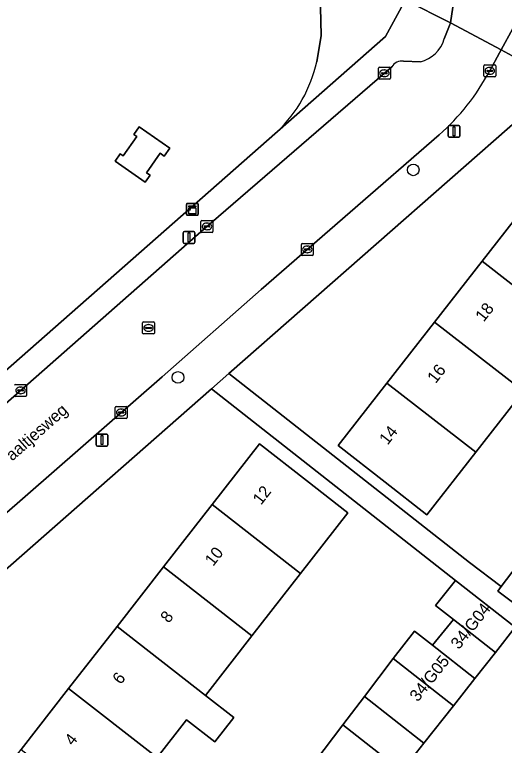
# Model space of a CAD drawing. Extents: x 158352 to 159489, y 383828 to 384603.
# Drawn here: x 158947.7 to 158988.7, y 383938.1 to 383999.4 of the extents above; entities that cross this region are included whole.
import ezdxf

# ---------------------------------------------------------------- set-up
doc = ezdxf.new("R2010")
doc.units = 0
for name, color, linetype in [('IMGEO_Boom', 7, 'Continuous'), ('IMGEO_Erf', 7, 'Continuous'), ('IMGEO_Kast', 7, 'Continuous'), ('IMGEO_Kolk', 7, 'Continuous'), ('IMGEO_Lichtmast', 7, 'Continuous'), ('IMGEO_Openbare_ruimte_label', 7, 'Continuous'), ('IMGEO_Pand', 7, 'Continuous'), ('IMGEO_Pand_nummerreeks', 7, 'Continuous'), ('IMGEO_Rijbaan_lokaal_open', 7, 'Continuous'), ('IMGEO_Rioolput', 7, 'Continuous'), ('IMGEO_Voetpad_open', 7, 'Continuous')]:
    doc.layers.add(name, color=color, linetype=linetype)

msp = doc.modelspace()

# ---------------------------------------------------------------- linework, layer by layer
at = {"layer": 'IMGEO_Boom'}
for centre in [(158981.095, 383986.358), (158961.37, 383968.951)]:
    msp.add_circle(centre, 0.489, dxfattribs=at)
at = {"layer": 'IMGEO_Erf'}
for points in [[(158973.009, 383995.42), (158973.387, 383997.64), (158973.32, 384000), (158973.14, 384001.022)], [(158990.338, 383990.981), (158965.629, 383969.277), (158985.803, 383953.421), (158988.471, 383951.405), (158990.338, 383953.876)], [(158930.848, 383955.369), (158969.722, 383989.587)], [(158989.64, 383947.992), (158987.979, 383945.879), (158986.26, 383943.692), (158984.462, 383941.404), (158981.991, 383938.261), (158980.149, 383935.918), (158977.736, 383932.848), (158975.883, 383930.491), (158973.579, 383927.56), (158971.799, 383925.296), (158967.465, 383919.782), (158965.698, 383917.535), (158963.842, 383915.174), (158962.945, 383914.033), (158962.844, 383913.905), (158957.903, 383917.789), (158931.11, 383938.956), (158928.107, 383936.318)]]:
    msp.add_lwpolyline(points, dxfattribs=at)
for points in [[(158957.915, 383989.146), (158957.664, 383989.323), (158958.125, 383989.98), (158960.688, 383988.18), (158960.221, 383987.515), (158959.884, 383987.752), (158958.734, 383986.115), (158959.033, 383985.904), (158958.623, 383985.321), (158956.103, 383987.091), (158956.529, 383987.697), (158956.775, 383987.524)], [(158978.734, 383960.163), (158974.793, 383963.24), (158978.88, 383968.476), (158982.869, 383973.585), (158986.865, 383978.704), (158990.865, 383983.828), (158994.938, 383989.045), (159000, 383985.129), (159002.421, 383983.256), (159000, 383980.156), (158999.344, 383979.316), (158998.321, 383978.008), (158994.317, 383972.887), (158990.329, 383967.786), (158986.331, 383962.673), (158982.233, 383957.432)], [(158972.846, 383936.692), (158975.198, 383939.809), (158976.994, 383942.189), (158979.401, 383945.379), (158981.199, 383947.667), (158982.703, 383946.486), (158984.473, 383948.633), (158982.969, 383949.814), (158984.631, 383951.929), (158964.179, 383968.004), (158932.342, 383940.038), (158957.085, 383920.484), (158958.903, 383919.055), (158960.759, 383921.417), (158962.534, 383923.657), (158966.89, 383929.155), (158968.678, 383931.413), (158970.993, 383934.335)], [(158951.535, 383926.727), (158948.064, 383929.436), (158944.123, 383932.513), (158948.212, 383937.751), (158952.206, 383942.867), (158956.262, 383948.062), (158960.164, 383953.061), (158964.243, 383958.286), (158968.21, 383963.367), (158972.151, 383960.29), (158975.621, 383957.581), (158971.654, 383952.5), (158967.575, 383947.275), (158963.673, 383942.276), (158966.051, 383940.42), (158964.461, 383938.383), (158962.084, 383940.24), (158959.618, 383937.081), (158955.624, 383931.965)]]:
    msp.add_lwpolyline(points, close=True, dxfattribs=at)
msp.add_arc((158961.562, 383998.028), 11.74, 314.03062, 347.16531, dxfattribs=at)
at = {"layer": 'IMGEO_Kast'}
for p, q in [((158962.075, 383982.624), (158962.075, 383983.465)), ((158962.075, 383983.465), (158962.075, 383982.624)), ((158962.15, 383983.549), (158962.991, 383983.549)), ((158962.991, 383983.549), (158962.15, 383983.549)), ((158963.075, 383983.474), (158963.075, 383982.633)), ((158963.075, 383982.633), (158963.075, 383983.474)), ((158963, 383982.549), (158962.159, 383982.549)), ((158962.159, 383982.549), (158963, 383982.549))]:
    msp.add_line(p, q, dxfattribs=at)
for points in [[(158962.27, 383983.339), (158962.87, 383983.339), (158962.87, 383983.254), (158962.27, 383983.254), (158962.27, 383983.339)], [(158962.27, 383983.164), (158962.87, 383983.164), (158962.87, 383982.675), (158962.27, 383982.675), (158962.27, 383983.164)]]:
    msp.add_lwpolyline(points, dxfattribs=at)
msp.add_circle((158962.354, 383983.013), 0.0377, dxfattribs=at)
for centre, start, end in [((158962.153, 383983.471), 92.4484, 184.28452), ((158962.153, 383983.471), 92.4484, 184.28452), ((158962.997, 383983.471), 2.4484, 94.28452), ((158962.997, 383983.471), 2.4484, 94.28452), ((158962.153, 383982.627), 182.4484, 274.28452), ((158962.153, 383982.627), 182.4484, 274.28452), ((158962.997, 383982.627), 272.4484, 4.28452), ((158962.997, 383982.627), 272.4484, 4.28452)]:
    msp.add_arc(centre, 0.0779, start, end, dxfattribs=at)
at = {"layer": 'IMGEO_Kolk'}
for p, q in [((158978.177, 383994.039), (158978.177, 383994.891)), ((158978.252, 383994.965), (158979.104, 383994.965)), ((158979.178, 383994.891), (158979.178, 383994.039)), ((158987.007, 383994.238), (158987.007, 383995.09)), ((158987.082, 383995.164), (158987.934, 383995.164)), ((158987.495, 383994.944), (158987.52, 383994.944)), ((158988.008, 383995.09), (158988.008, 383994.238)), ((158978.436, 383994.459), (158978.436, 383994.471)), ((158978.874, 383994.422), (158978.476, 383994.422)), ((158978.479, 383994.508), (158978.877, 383994.508)), ((158978.688, 383994.185), (158978.663, 383994.185)), ((158978.665, 383994.745), (158978.69, 383994.745)), ((158978.92, 383994.471), (158978.92, 383994.459)), ((158987.934, 383994.164), (158987.082, 383994.164)), ((158987.266, 383994.658), (158987.266, 383994.67)), ((158987.704, 383994.621), (158987.306, 383994.621)), ((158987.309, 383994.707), (158987.707, 383994.707)), ((158987.518, 383994.384), (158987.493, 383994.384)), ((158987.75, 383994.67), (158987.75, 383994.658)), ((158979.104, 383993.965), (158978.252, 383993.965)), ((158963.299, 383981.188), (158963.299, 383982.04)), ((158963.374, 383982.114), (158964.226, 383982.114)), ((158964.3, 383982.04), (158964.3, 383981.188)), ((158963.558, 383981.608), (158963.558, 383981.62)), ((158963.996, 383981.571), (158963.598, 383981.571)), ((158963.601, 383981.657), (158963.999, 383981.657)), ((158963.81, 383981.334), (158963.785, 383981.334)), ((158963.787, 383981.894), (158963.812, 383981.894)), ((158964.042, 383981.62), (158964.042, 383981.608)), ((158964.226, 383981.114), (158963.374, 383981.114)), ((158971.711, 383979.26), (158971.711, 383980.112)), ((158971.786, 383980.186), (158972.638, 383980.186)), ((158972.712, 383980.112), (158972.712, 383979.26)), ((158971.97, 383979.68), (158971.97, 383979.692)), ((158972.408, 383979.643), (158972.01, 383979.643)), ((158972.013, 383979.729), (158972.411, 383979.729)), ((158972.199, 383979.966), (158972.224, 383979.966)), ((158972.454, 383979.692), (158972.454, 383979.68)), ((158972.638, 383979.186), (158971.786, 383979.186)), ((158972.222, 383979.406), (158972.197, 383979.406)), ((158947.751, 383968.361), (158948.603, 383968.361)), ((158947.935, 383967.855), (158947.935, 383967.867)), ((158948.373, 383967.818), (158947.975, 383967.818)), ((158947.978, 383967.904), (158948.376, 383967.904)), ((158948.164, 383968.141), (158948.189, 383968.141)), ((158948.419, 383967.867), (158948.419, 383967.855)), ((158948.677, 383968.287), (158948.677, 383967.435)), ((158948.603, 383967.361), (158947.751, 383967.361)), ((158948.187, 383967.581), (158948.162, 383967.581)), ((158956.109, 383965.582), (158956.109, 383966.434)), ((158956.184, 383966.508), (158957.036, 383966.508)), ((158956.368, 383966.002), (158956.368, 383966.014)), ((158956.806, 383965.965), (158956.408, 383965.965)), ((158956.411, 383966.051), (158956.809, 383966.051)), ((158956.597, 383966.288), (158956.622, 383966.288)), ((158956.852, 383966.014), (158956.852, 383966.002)), ((158957.11, 383966.434), (158957.11, 383965.582)), ((158957.036, 383965.508), (158956.184, 383965.508)), ((158956.62, 383965.728), (158956.595, 383965.728))]:
    msp.add_line(p, q, dxfattribs=at)
for points in [[(158978.177, 383994.039), (158978.177, 383994.891)], [(158978.252, 383994.965), (158979.104, 383994.965)], [(158979.178, 383994.891), (158979.178, 383994.039)], [(158987.007, 383994.238), (158987.007, 383995.09)], [(158987.082, 383995.164), (158987.934, 383995.164)], [(158988.008, 383995.09), (158988.008, 383994.238)], [(158987.934, 383994.164), (158987.082, 383994.164)], [(158979.104, 383993.965), (158978.252, 383993.965)], [(158963.299, 383981.188), (158963.299, 383982.04)], [(158963.374, 383982.114), (158964.226, 383982.114)], [(158964.3, 383982.04), (158964.3, 383981.188)], [(158964.226, 383981.114), (158963.374, 383981.114)], [(158971.711, 383979.26), (158971.711, 383980.112)], [(158971.786, 383980.186), (158972.638, 383980.186)], [(158972.712, 383980.112), (158972.712, 383979.26)], [(158972.638, 383979.186), (158971.786, 383979.186)], [(158947.751, 383968.361), (158948.603, 383968.361)], [(158948.677, 383968.287), (158948.677, 383967.435)], [(158948.603, 383967.361), (158947.751, 383967.361)], [(158956.109, 383965.582), (158956.109, 383966.434)], [(158956.184, 383966.508), (158957.036, 383966.508)], [(158957.11, 383966.434), (158957.11, 383965.582)], [(158957.036, 383965.508), (158956.184, 383965.508)]]:
    msp.add_lwpolyline(points, dxfattribs=at)
for centre, radius, start, end in [((158978.254, 383994.889), 0.0765, 91.55205, 178.44795), ((158978.254, 383994.889), 0.0765, 91.55205, 178.44795), ((158979.102, 383994.889), 0.0765, 1.55205, 88.44795), ((158979.102, 383994.889), 0.0765, 1.55205, 88.44795), ((158987.084, 383995.088), 0.0765, 91.55205, 178.44795), ((158987.084, 383995.088), 0.0765, 91.55205, 178.44795), ((158987.932, 383995.088), 0.0765, 1.55205, 88.44795), ((158987.932, 383995.088), 0.0765, 1.55205, 88.44795), ((158978.476, 383994.468), 0.0403, 85.87752, 175.75265), ((158978.473, 383994.458), 0.0366, 178.93798, 274.71019), ((158978.877, 383994.465), 0.043, 264.86636, 352.45326), ((158978.881, 383994.47), 0.0386, 1.73085, 96.63898), ((158987.084, 383994.24), 0.0765, 181.55205, 268.44795), ((158987.084, 383994.24), 0.0765, 181.55205, 268.44795), ((158987.306, 383994.667), 0.0403, 85.87752, 175.75265), ((158987.303, 383994.657), 0.0366, 178.93798, 274.71019), ((158987.707, 383994.664), 0.043, 264.86636, 352.45326), ((158987.711, 383994.669), 0.0386, 1.73085, 96.63898), ((158987.932, 383994.24), 0.0765, 271.55205, 358.44795), ((158987.932, 383994.24), 0.0765, 271.55205, 358.44795), ((158978.254, 383994.041), 0.0765, 181.55205, 268.44795), ((158978.254, 383994.041), 0.0765, 181.55205, 268.44795), ((158979.102, 383994.041), 0.0765, 271.55205, 358.44795), ((158979.102, 383994.041), 0.0765, 271.55205, 358.44795), ((158963.376, 383982.038), 0.0765, 91.55205, 178.44795), ((158963.376, 383982.038), 0.0765, 91.55205, 178.44795), ((158964.224, 383982.038), 0.0765, 1.55205, 88.44795), ((158964.224, 383982.038), 0.0765, 1.55205, 88.44795), ((158963.598, 383981.617), 0.0403, 85.87752, 175.75265), ((158963.595, 383981.607), 0.0366, 178.93798, 274.71019), ((158963.999, 383981.614), 0.043, 264.86636, 352.45326), ((158964.003, 383981.619), 0.0386, 1.73085, 96.63898), ((158963.376, 383981.19), 0.0765, 181.55205, 268.44795), ((158963.376, 383981.19), 0.0765, 181.55205, 268.44795), ((158964.224, 383981.19), 0.0765, 271.55205, 358.44795), ((158964.224, 383981.19), 0.0765, 271.55205, 358.44795), ((158971.788, 383980.11), 0.0765, 91.55205, 178.44795), ((158971.788, 383980.11), 0.0765, 91.55205, 178.44795), ((158972.636, 383980.11), 0.0765, 1.55205, 88.44795), ((158972.636, 383980.11), 0.0765, 1.55205, 88.44795), ((158972.01, 383979.689), 0.0403, 85.87752, 175.75265), ((158972.007, 383979.679), 0.0366, 178.93798, 274.71019), ((158972.411, 383979.686), 0.043, 264.86636, 352.45326), ((158972.415, 383979.691), 0.0386, 1.73085, 96.63898), ((158971.788, 383979.262), 0.0765, 181.55205, 268.44795), ((158971.788, 383979.262), 0.0765, 181.55205, 268.44795), ((158972.636, 383979.262), 0.0765, 271.55205, 358.44795), ((158972.636, 383979.262), 0.0765, 271.55205, 358.44795), ((158947.753, 383968.285), 0.0765, 91.55205, 178.44795), ((158947.753, 383968.285), 0.0765, 91.55205, 178.44795), ((158947.975, 383967.864), 0.0403, 85.87752, 175.75265), ((158947.972, 383967.854), 0.0366, 178.93798, 274.71019), ((158948.376, 383967.861), 0.043, 264.86636, 352.45326), ((158948.38, 383967.866), 0.0386, 1.73085, 96.63898), ((158948.601, 383968.285), 0.0765, 1.55205, 88.44795), ((158948.601, 383968.285), 0.0765, 1.55205, 88.44795), ((158947.753, 383967.437), 0.0765, 181.55205, 268.44795), ((158947.753, 383967.437), 0.0765, 181.55205, 268.44795), ((158948.601, 383967.437), 0.0765, 271.55205, 358.44795), ((158948.601, 383967.437), 0.0765, 271.55205, 358.44795), ((158956.186, 383966.432), 0.0765, 91.55205, 178.44795), ((158956.186, 383966.432), 0.0765, 91.55205, 178.44795), ((158956.408, 383966.011), 0.0403, 85.87752, 175.75265), ((158956.405, 383966.001), 0.0366, 178.93798, 274.71019), ((158956.809, 383966.008), 0.043, 264.86636, 352.45326), ((158956.813, 383966.013), 0.0386, 1.73085, 96.63898), ((158957.034, 383966.432), 0.0765, 1.55205, 88.44795), ((158957.034, 383966.432), 0.0765, 1.55205, 88.44795), ((158956.186, 383965.584), 0.0765, 181.55205, 268.44795), ((158956.186, 383965.584), 0.0765, 181.55205, 268.44795), ((158957.034, 383965.584), 0.0765, 271.55205, 358.44795), ((158957.034, 383965.584), 0.0765, 271.55205, 358.44795)]:
    msp.add_arc(centre, radius, start, end, dxfattribs=at)
for centre, major_axis, ratio, start_param, end_param in [((158987.494, 383994.664), (-0.387, 0.002), 0.722429, 4.712389, 7.853982), ((158987.519, 383994.664), (-0.39, 0.002), 0.717154, 1.570796, 4.712389), ((158978.664, 383994.465), (-0.387, 0.002), 0.722429, 4.712389, 7.853982), ((158978.689, 383994.465), (-0.39, 0.002), 0.717154, 1.570796, 4.712389), ((158963.786, 383981.614), (-0.387, 0.002), 0.722429, 4.712389, 7.853982), ((158963.811, 383981.614), (-0.39, 0.002), 0.717154, 1.570796, 4.712389), ((158972.198, 383979.686), (-0.387, 0.002), 0.722429, 4.712389, 7.853982), ((158972.223, 383979.686), (-0.39, 0.002), 0.717154, 1.570796, 4.712389), ((158948.163, 383967.861), (-0.387, 0.002), 0.722429, 4.712389, 7.853982), ((158948.188, 383967.861), (-0.39, 0.002), 0.717154, 1.570796, 4.712389), ((158956.596, 383966.008), (-0.387, 0.002), 0.722429, 4.712389, 7.853982), ((158956.621, 383966.008), (-0.39, 0.002), 0.717154, 1.570796, 4.712389)]:
    msp.add_ellipse(centre, major_axis=major_axis, ratio=ratio, start_param=start_param, end_param=end_param, dxfattribs=at)
at = {"layer": 'IMGEO_Lichtmast'}
for p, q in [((158984.01, 383989.191), (158984.01, 383989.991)), ((158984.01, 383989.991), (158984.01, 383989.191)), ((158984.11, 383990.091), (158984.9, 383990.091)), ((158984.9, 383990.091), (158984.11, 383990.091)), ((158985, 383989.991), (158985, 383989.191)), ((158985, 383989.191), (158985, 383989.991)), ((158984.9, 383989.091), (158984.11, 383989.091)), ((158984.11, 383989.091), (158984.9, 383989.091)), ((158961.803, 383980.291), (158961.803, 383981.091)), ((158961.803, 383981.091), (158961.803, 383980.291)), ((158961.903, 383981.191), (158962.693, 383981.191)), ((158962.693, 383981.191), (158961.903, 383981.191)), ((158962.793, 383981.091), (158962.793, 383980.291)), ((158962.793, 383980.291), (158962.793, 383981.091)), ((158962.693, 383980.191), (158961.903, 383980.191)), ((158961.903, 383980.191), (158962.693, 383980.191)), ((158954.61, 383964.194), (158955.4, 383964.194)), ((158955.4, 383964.194), (158954.61, 383964.194)), ((158954.51, 383963.294), (158954.51, 383964.094)), ((158954.51, 383964.094), (158954.51, 383963.294)), ((158955.5, 383964.094), (158955.5, 383963.294)), ((158955.5, 383963.294), (158955.5, 383964.094)), ((158955.4, 383963.194), (158954.61, 383963.194)), ((158954.61, 383963.194), (158955.4, 383963.194))]:
    msp.add_line(p, q, dxfattribs=at)
for points in [[(158984.43, 383989.966), (158984.58, 383989.966), (158984.58, 383989.216), (158984.43, 383989.216), (158984.43, 383989.966)], [(158962.223, 383981.066), (158962.373, 383981.066), (158962.373, 383980.316), (158962.223, 383980.316), (158962.223, 383981.066)], [(158954.93, 383964.069), (158955.08, 383964.069), (158955.08, 383963.319), (158954.93, 383963.319), (158954.93, 383964.069)]]:
    msp.add_lwpolyline(points, dxfattribs=at)
for centre, start, end in [((158984.11, 383989.991), 90, 180), ((158984.11, 383989.991), 90, 180), ((158984.9, 383989.991), 0, 90), ((158984.9, 383989.991), 360, 90), ((158984.11, 383989.191), 180, 270), ((158984.11, 383989.191), 180, 270), ((158984.9, 383989.191), 270, 0), ((158984.9, 383989.191), 270, 0), ((158961.903, 383981.091), 90, 180), ((158961.903, 383981.091), 90, 180), ((158962.693, 383981.091), 0, 90), ((158962.693, 383981.091), 360, 90), ((158961.903, 383980.291), 180, 270), ((158961.903, 383980.291), 180, 270), ((158962.693, 383980.291), 270, 0), ((158962.693, 383980.291), 270, 0), ((158954.61, 383964.094), 90, 180), ((158954.61, 383964.094), 90, 180), ((158955.4, 383964.094), 0, 90), ((158955.4, 383964.094), 360, 90), ((158954.61, 383963.294), 180, 270), ((158954.61, 383963.294), 180, 270), ((158955.4, 383963.294), 270, 0), ((158955.4, 383963.294), 270, 0)]:
    msp.add_arc(centre, 0.1, start, end, dxfattribs=at)
at = {"layer": 'IMGEO_Pand'}
for points in [[(158958.623, 383985.321), (158959.033, 383985.904), (158958.734, 383986.115), (158959.884, 383987.752), (158960.221, 383987.515), (158960.688, 383988.18), (158958.125, 383989.98), (158957.664, 383989.323), (158957.915, 383989.146), (158956.775, 383987.524), (158956.529, 383987.697), (158956.103, 383987.091)], [(158994.317, 383972.887), (158998.321, 383978.008), (158990.865, 383983.828), (158986.865, 383978.704)], [(158994.317, 383972.887), (158986.865, 383978.704), (158982.869, 383973.585), (158990.329, 383967.786)], [(158978.88, 383968.476), (158986.331, 383962.673), (158990.329, 383967.786), (158982.869, 383973.585)], [(158978.88, 383968.476), (158974.793, 383963.24), (158978.734, 383960.163), (158982.233, 383957.432), (158986.331, 383962.673)], [(158971.654, 383952.5), (158975.621, 383957.581), (158972.151, 383960.29), (158968.21, 383963.367), (158964.243, 383958.286)], [(158960.164, 383953.061), (158967.575, 383947.275), (158971.654, 383952.5), (158964.243, 383958.286)], [(158992.681, 383952.105), (158990.338, 383953.876), (158988.471, 383951.405), (158988.182, 383951.022), (158990.526, 383949.252)], [(158956.262, 383948.062), (158963.673, 383942.276), (158967.575, 383947.275), (158960.164, 383953.061)], [(158984.631, 383951.929), (158982.969, 383949.814), (158984.473, 383948.633), (158987.979, 383945.879), (158989.64, 383947.992)], [(158984.473, 383948.633), (158982.703, 383946.486), (158986.26, 383943.692), (158987.979, 383945.879)], [(158956.262, 383948.062), (158952.206, 383942.867), (158959.618, 383937.081), (158962.084, 383940.24), (158964.461, 383938.383), (158966.051, 383940.42), (158963.673, 383942.276)], [(158982.703, 383946.486), (158981.199, 383947.667), (158979.401, 383945.379), (158984.462, 383941.404), (158986.26, 383943.692)], [(158979.401, 383945.379), (158976.994, 383942.189), (158981.991, 383938.261), (158984.462, 383941.404)], [(158959.618, 383937.081), (158952.206, 383942.867), (158948.212, 383937.751), (158955.624, 383931.965)], [(158976.994, 383942.189), (158975.198, 383939.809), (158980.149, 383935.918), (158981.991, 383938.261)], [(158975.198, 383939.809), (158972.846, 383936.692), (158977.736, 383932.848), (158980.149, 383935.918)]]:
    msp.add_lwpolyline(points, close=True, dxfattribs=at)
at = {"layer": 'IMGEO_Rijbaan_lokaal_open'}
for points in [[(158984.418, 384000), (158984.218, 383998.68), (158988.465, 383996.422), (158990.415, 384000), (158993.062, 384004.962), (158985.55, 384009.06)], [(158987.501, 383994.653), (158988.327, 383996.169), (158988.465, 383996.422), (158984.218, 383998.68), (158984.13, 383998.455), (158983.69, 383997.336)], [(158981.694, 383995.433), (158980.285, 383995.463)], [(158979.284, 383994.988), (158963.526, 383981.375), (158932.122, 383953.722)], [(158960.04, 383969.004), (158968.343, 383976.328), (158983.266, 383989.284)], [(158926.205, 383939.436), (158933.072, 383945.457), (158960.04, 383969.004)]]:
    msp.add_lwpolyline(points, dxfattribs=at)
for centre, radius, start, end in [((158981.026, 383998.132), 2.78, 283.90181, 343.36544), ((158980.122, 383994.515), 0.962, 80.21809, 150.55298), ((158970.079, 384004.041), 19.79, 311.78527, 331.68286)]:
    msp.add_arc(centre, radius, start, end, dxfattribs=at)
at = {"layer": 'IMGEO_Rioolput'}
for p, q in [((158958.401, 383972.673), (158958.401, 383973.525)), ((158958.476, 383973.599), (158959.328, 383973.599)), ((158958.889, 383973.379), (158958.914, 383973.379)), ((158959.402, 383973.525), (158959.402, 383972.673)), ((158958.66, 383973.093), (158958.66, 383973.105)), ((158959.098, 383973.056), (158958.7, 383973.056)), ((158958.703, 383973.142), (158959.101, 383973.142)), ((158958.912, 383972.819), (158958.887, 383972.819)), ((158959.144, 383973.105), (158959.144, 383973.093)), ((158959.328, 383972.599), (158958.476, 383972.599))]:
    msp.add_line(p, q, dxfattribs=at)
for points in [[(158958.401, 383972.673), (158958.401, 383973.525)], [(158958.476, 383973.599), (158959.328, 383973.599)], [(158959.402, 383973.525), (158959.402, 383972.673)], [(158959.328, 383972.599), (158958.476, 383972.599)]]:
    msp.add_lwpolyline(points, dxfattribs=at)
for centre, radius, start, end in [((158958.478, 383973.523), 0.0765, 91.55205, 178.44795), ((158958.478, 383973.523), 0.0765, 91.55205, 178.44795), ((158959.326, 383973.523), 0.0765, 1.55205, 88.44795), ((158959.326, 383973.523), 0.0765, 1.55205, 88.44795), ((158958.7, 383973.102), 0.0403, 85.87752, 175.75265), ((158958.697, 383973.092), 0.0366, 178.93798, 274.71019), ((158959.101, 383973.099), 0.043, 264.86636, 352.45326), ((158959.105, 383973.104), 0.0386, 1.73085, 96.63898), ((158958.478, 383972.675), 0.0765, 181.55205, 268.44795), ((158958.478, 383972.675), 0.0765, 181.55205, 268.44795), ((158959.326, 383972.675), 0.0765, 271.55205, 358.44795), ((158959.326, 383972.675), 0.0765, 271.55205, 358.44795)]:
    msp.add_arc(centre, radius, start, end, dxfattribs=at)
for centre, major_axis, ratio, start_param, end_param in [((158958.888, 383973.099), (-0.387, 0.002), 0.722429, 4.712389, 7.853982), ((158958.913, 383973.099), (-0.39, 0.002), 0.717154, 1.570796, 4.712389)]:
    msp.add_ellipse(centre, major_axis=major_axis, ratio=ratio, start_param=start_param, end_param=end_param, dxfattribs=at)
at = {"layer": 'IMGEO_Voetpad_open'}
for points in [[(158915.838, 384035.986), (158917.741, 384035.003), (158968.65, 384007.096), (158980.456, 384000.624), (158984.218, 383998.68), (158984.418, 384000)], [(158969.722, 383989.587), (158978.773, 383997.554), (158980.114, 384000), (158980.456, 384000.624), (158968.65, 384007.096)], [(158973.14, 384001.022), (158973.32, 384000), (158973.387, 383997.64), (158973.009, 383995.42)], [(158983.69, 383997.336), (158984.13, 383998.455), (158984.218, 383998.68), (158980.456, 384000.624), (158980.114, 384000), (158978.773, 383997.554), (158969.722, 383989.587), (158930.848, 383955.369), (158930.218, 383952.85)], [(158996.221, 383991.872), (158989.381, 383995.929), (158988.465, 383996.422), (158988.327, 383996.169), (158987.501, 383994.653)], [(158980.285, 383995.463), (158981.694, 383995.433)], [(158932.122, 383953.722), (158963.526, 383981.375), (158979.284, 383994.988)], [(158931.11, 383938.956), (158932.342, 383940.038), (158964.179, 383968.004), (158965.629, 383969.277), (158990.338, 383990.981)], [(158983.266, 383989.284), (158968.343, 383976.328), (158960.04, 383969.004), (158933.072, 383945.457), (158926.205, 383939.436)]]:
    msp.add_lwpolyline(points, dxfattribs=at)
for points in [[(158994.468, 384005.38), (158990.258, 384007.677), (158986.048, 384009.973), (158985.55, 384009.06), (158993.062, 384004.962), (158990.415, 384000), (158988.465, 383996.422), (158989.381, 383995.929), (158992.625, 384001.956)], [(158965.629, 383969.277), (158964.179, 383968.004), (158984.631, 383951.929), (158989.64, 383947.992), (158990.526, 383949.252), (158988.182, 383951.022), (158988.471, 383951.405), (158985.803, 383953.421)]]:
    msp.add_lwpolyline(points, close=True, dxfattribs=at)
for centre, radius, start, end in [((158981.026, 383998.132), 2.78, 283.90181, 343.36544), ((158961.562, 383998.028), 11.74, 314.03062, 347.16531), ((158980.122, 383994.515), 0.962, 80.21809, 150.55298), ((158970.079, 384004.041), 19.79, 311.78527, 331.68286)]:
    msp.add_arc(centre, radius, start, end, dxfattribs=at)

# ---------------------------------------------------------------- texts
at = {"layer": 'IMGEO_Openbare_ruimte_label'}
msp.add_text('Paaltjesweg', height=1, rotation=41.35294, dxfattribs=at).set_placement((158946.803, 383961.305))
at = {"layer": 'IMGEO_Pand_nummerreeks'}
for s, rotation, p in [('18', 52.02217, (158986.999, 383973.547)), ('16', 52.02217, (158982.969, 383968.383)), ('14', 52.02217, (158978.94, 383963.222)), ('12', 52.02167, (158968.334, 383958.195)), ('10', 52.02167, (158964.322, 383953.058)), ('34/G04', 51.82976, (158984.926, 383946.074)), ('8', 52.02167, (158960.592, 383948.28)), ('34/G05', 51.83549, (158981.478, 383941.685)), ('6', 52.01884, (158956.575, 383943.134)), ('4', 52.02167, (158952.561, 383937.992))]:
    msp.add_text(s, height=1, rotation=rotation, dxfattribs=at).set_placement(p)

doc.saveas('drawing.dxf')
